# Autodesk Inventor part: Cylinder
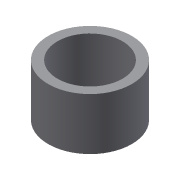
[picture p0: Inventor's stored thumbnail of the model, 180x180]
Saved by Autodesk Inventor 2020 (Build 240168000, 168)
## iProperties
Part Number: Cylinder
Document SubType Name: Modeling
Created: 2003-01
Designer: Owner
Density: 1 g/cm^3
Material: Generic
Appearance: Default
Control State: 0
Master: False
Checked Out: False
Shininess: 64.0
Length Units: 11269
Angle Units: 11279
Time Units: 11290
Mass Units: 11283
Length Display Precision: 3
Angle Display Precision: 2
Compacted: True
Density: 0.0
Volumn: 0.0
Area: 0.0
PropertySet Name: Model Information
Author: Owner
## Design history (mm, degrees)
sketch "Sketch1"
  geometry: C1 r 112.5 at (0, 0); C2 r 87.5 at (0, 0)
  constraints: 2 centre point, 1 coincident, 1 concentric
  dimensions: "d0" = 225 diameter of C1; "d1" = 175 diameter of C2
extrude "Extrusion1" new body sketch "Sketch1" stored distance "d2" = 140; taper "d3" = 0 deg
body "Solid1"
